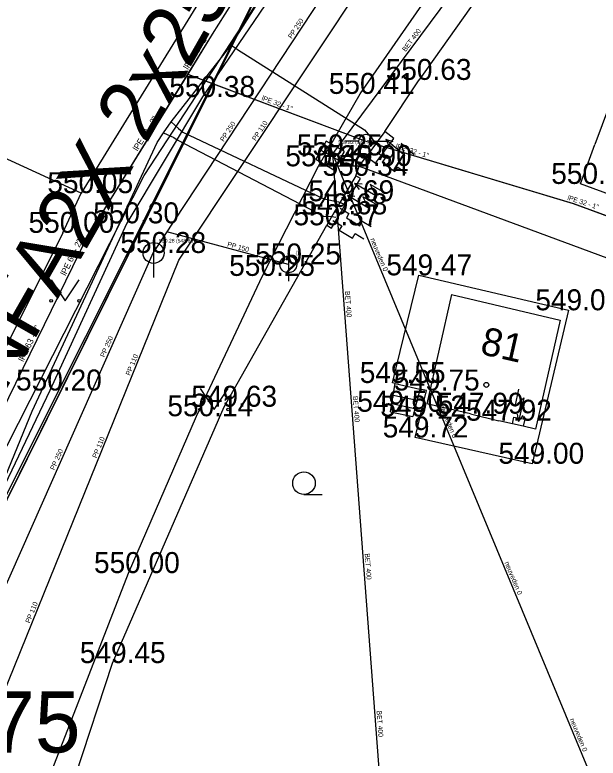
# Model space of a CAD drawing. Extents: x -669995 to -669686, y -1125551 to -1125263.
# Drawn here: x -669817.31 to -669796.45, y -1125325.67 to -1125299.08 of the extents above; entities that cross this region are included whole.
import ezdxf

# ---------------------------------------------------------------- set-up
doc = ezdxf.new("R2010")
doc.units = 0
for name, color, linetype in [('G_Bod_tecka', 7, 'Continuous'), ('G_Bod_vyska', 7, 'Continuous'), ('G_Budovy-znacky', 7, 'Continuous'), ('G_Budovy_Objekty', 7, 'Continuous'), ('G_Budovy_vstupy', 7, 'Continuous'), ('G_Cesty_Schody', 7, 'Continuous'), ('G_Cisla_jina', 7, 'Continuous'), ('G_Plochy_zpevnene', 7, 'Continuous'), ('G_Ploty', 7, 'Continuous'), ('G_Ploty_vstupy', 7, 'Continuous'), ('G_Site-kanalizace', 7, 'Continuous'), ('G_Site-Rozvadece', 7, 'Continuous'), ('G_Site-vodovod', 7, 'Continuous'), ('G_Z_ELsilove_nadz_kotovane', 7, 'Continuous'), ('G_Z_ELsilove_podz_kotovane', 7, 'Continuous'), ('G_Z_KANAL_podz_kotovane', 7, 'Continuous'), ('G_Z_KANAL_podz_priblizne', 7, 'Continuous'), ('G_Z_PLYNY_podz_geodeticky', 7, 'Continuous'), ('G_Z_SPOJE_podz_geodeticky', 7, 'Continuous'), ('G_Z_SPOJE_podz_kotovane', 7, 'Continuous'), ('G_Z_SPOJE_podz_priblizne', 7, 'Continuous'), ('G_Z_VODA_podz_kotovane', 7, 'Continuous'), ('G_Zelen-Znacky', 7, 'Continuous'), ('Vrstva 11', 7, 'Continuous'), ('Vrstva 17', 7, 'Continuous'), ('Vrstva 2', 7, 'Continuous'), ('Vrstva 21', 7, 'Continuous'), ('Vrstva 25', 7, 'Continuous'), ('Vrstva 26', 7, 'Continuous'), ('Vrstva 3', 7, 'Continuous'), ('Vrstva 4', 7, 'Continuous'), ('Vrstva 5', 7, 'Continuous'), ('Vrstva 6', 7, 'Continuous'), ('Vrstva 8', 7, 'Continuous')]:
    doc.layers.add(name, color=color, linetype=linetype)

msp = doc.modelspace()

# ---------------------------------------------------------------- linework, layer by layer
at = {"layer": 'G_Bod_tecka'}
for p, q in [((-669802.85, -1125301.41), (-669802.85, -1125301.41)), ((-669810.6, -1125302.02), (-669810.6, -1125302.02)), ((-669804.96, -1125301.91), (-669804.96, -1125301.91)), ((-669806.04, -1125304.11), (-669806.04, -1125304.11)), ((-669805, -1125304.49), (-669805, -1125304.49)), ((-669806.45, -1125304.5), (-669806.45, -1125304.5)), ((-669805.12, -1125304.84), (-669805.12, -1125304.84)), ((-669797.09, -1125305.13), (-669797.09, -1125305.13)), ((-669814.94, -1125305.46), (-669814.94, -1125305.46)), ((-669805.63, -1125305.75), (-669805.63, -1125305.75)), ((-669805.88, -1125306.22), (-669805.88, -1125306.22)), ((-669813.3, -1125306.54), (-669813.3, -1125306.54)), ((-669806.16, -1125306.61), (-669806.16, -1125306.61)), ((-669815.59, -1125306.88), (-669815.59, -1125306.88)), ((-669812.35, -1125307.6), (-669812.35, -1125307.6)), ((-669807.53, -1125308.01), (-669807.53, -1125308.01)), ((-669808.46, -1125308.42), (-669808.46, -1125308.42)), ((-669802.86, -1125308.4), (-669802.86, -1125308.4)), ((-669797.51, -1125309.65), (-669797.51, -1125309.65)), ((-669803.81, -1125312.25), (-669803.81, -1125312.25)), ((-669816.06, -1125312.52), (-669816.06, -1125312.52)), ((-669802.59, -1125312.52), (-669802.59, -1125312.52)), ((-669809.82, -1125313.1), (-669809.82, -1125313.1)), ((-669810.81, -1125313.44), (-669810.81, -1125313.44)), ((-669803.88, -1125313.28), (-669803.88, -1125313.28)), ((-669803.08, -1125313.45), (-669803.08, -1125313.45)), ((-669801.02, -1125313.35), (-669801.02, -1125313.35)), ((-669800.01, -1125313.6), (-669800.01, -1125313.6)), ((-669802.99, -1125314.2), (-669802.99, -1125314.2)), ((-669798.81, -1125315.14), (-669798.81, -1125315.14)), ((-669813.25, -1125319.05), (-669813.25, -1125319.05)), ((-669813.82, -1125322.27), (-669813.82, -1125322.27))]:
    msp.add_line(p, q, dxfattribs=at)
at = {"layer": 'G_Budovy-znacky'}
msp.add_circle((-669800.45, -1125312.32), 0.0875, dxfattribs=at)
at = {"layer": 'G_Budovy_Objekty'}
for p, q in [((-669797.09, -1125305.13), (-669796.57, -1125303.72)), ((-669782.72, -1125310.4), (-669797.09, -1125305.13)), ((-669803.81, -1125312.25), (-669802.86, -1125308.4)), ((-669802.86, -1125308.4), (-669797.51, -1125309.65)), ((-669801.7, -1125309.09), (-669802.58, -1125313)), ((-669801.7, -1125309.09), (-669797.81, -1125310)), ((-669797.51, -1125309.65), (-669798.81, -1125315.14)), ((-669797.81, -1125310), (-669798.69, -1125313.9)), ((-669803.71, -1125312.27), (-669803.81, -1125312.25)), ((-669802.99, -1125314.2), (-669802.59, -1125312.52)), ((-669802.59, -1125312.52), (-669802.83, -1125312.47)), ((-669801.02, -1125313.35), (-669802.58, -1125313)), ((-669799.52, -1125313.71), (-669800.01, -1125313.6)), ((-669799.13, -1125313.8), (-669799.52, -1125313.71)), ((-669798.69, -1125313.9), (-669799.13, -1125313.8)), ((-669798.81, -1125315.14), (-669802.99, -1125314.2))]:
    msp.add_line(p, q, dxfattribs=at)
at = {"layer": 'G_Budovy_vstupy'}
for p, q in [((-669794.77, -1125298.84), (-669796.57, -1125303.72)), ((-669803.71, -1125312.27), (-669802.83, -1125312.47)), ((-669801.02, -1125313.35), (-669800.01, -1125313.6))]:
    msp.add_line(p, q, dxfattribs=at)
at = {"layer": 'G_Cesty_Schody'}
for p, q in [((-669803.78, -1125312.69), (-669803.71, -1125312.27)), ((-669803.83, -1125312.98), (-669803.78, -1125312.69)), ((-669803.78, -1125312.69), (-669802.93, -1125312.87)), ((-669802.83, -1125312.47), (-669802.93, -1125312.87)), ((-669803.88, -1125313.28), (-669803.83, -1125312.98)), ((-669803.83, -1125312.98), (-669803.01, -1125313.16)), ((-669802.93, -1125312.87), (-669803.01, -1125313.16)), ((-669803.01, -1125313.16), (-669803.08, -1125313.45)), ((-669803.88, -1125313.28), (-669803.08, -1125313.45))]:
    msp.add_line(p, q, dxfattribs=at)
at = {"layer": 'G_Plochy_zpevnene'}
for p, q in [((-669804.96, -1125301.91), (-669801.82, -1125297.37)), ((-669806.45, -1125304.5), (-669804.96, -1125301.91)), ((-669808.46, -1125308.42), (-669806.45, -1125304.5)), ((-669810.81, -1125313.44), (-669808.46, -1125308.42)), ((-669813.25, -1125319.05), (-669810.81, -1125313.44)), ((-669818.19, -1125331.78), (-669813.25, -1125319.05))]:
    msp.add_line(p, q, dxfattribs=at)
for points in [[(-669805.79, -1125294.93), (-669810.6, -1125302.02), (-669813.3, -1125306.54), (-669816.06, -1125312.52), (-669819.42, -1125319.54), (-669819.78, -1125320.24), (-669820.3, -1125320.5), (-669820.46, -1125320.59)], [(-669805, -1125304.49), (-669806.45, -1125304.5)]]:
    msp.add_lwpolyline(points, dxfattribs=at)
at = {"layer": 'G_Ploty'}
for p, q in [((-669805, -1125304.49), (-669804.73, -1125304.15)), ((-669805, -1125304.49), (-669788.56, -1125310.6)), ((-669809.82, -1125313.1), (-669806.16, -1125306.61)), ((-669815.59, -1125306.88), (-669822.31, -1125320.3)), ((-669813.82, -1125322.27), (-669809.82, -1125313.1)), ((-669817.15, -1125332.43), (-669813.82, -1125322.27))]:
    msp.add_line(p, q, dxfattribs=at)
for points in [[(-669809.61, -1125296.8), (-669814.94, -1125305.46)], [(-669804.08, -1125303.26), (-669802.85, -1125301.41)], [(-669814.94, -1125305.46), (-669819.49, -1125303.38)], [(-669805.12, -1125304.84), (-669805, -1125304.49)]]:
    msp.add_lwpolyline(points, dxfattribs=at)
at = {"layer": 'G_Ploty_vstupy'}
msp.add_line((-669815.59, -1125306.88), (-669814.94, -1125305.46), dxfattribs=at)
msp.add_lwpolyline([(-669796.56, -1125292.52), (-669802.85, -1125301.41)], dxfattribs=at)
at = {"layer": 'G_Site-kanalizace'}
for p, q in [((-669806.366, -1125303.924), (-669805.714, -1125304.296)), ((-669812.35, -1125307.225), (-669812.35, -1125308.475)), ((-669807.53, -1125307.71), (-669807.53, -1125308.61))]:
    msp.add_line(p, q, dxfattribs=at)
msp.add_lwpolyline([(-669806.551, -1125304.249), (-669805.899, -1125304.621), (-669805.528, -1125303.969), (-669806.18, -1125303.598)], close=True, dxfattribs=at)
for centre, radius in [((-669812.35, -1125307.6), 0.375), ((-669807.53, -1125308.01), 0.3)]:
    msp.add_circle(centre, radius, dxfattribs=at)
at = {"layer": 'G_Site-Rozvadece'}
for p, q in [((-669803.382, -1125304.117), (-669804.04, -1125303.539)), ((-669803.783, -1125303.619), (-669804.04, -1125303.539)), ((-669804.04, -1125303.539), (-669803.928, -1125303.783)), ((-669803.029, -1125304.095), (-669803.499, -1125303.681)), ((-669803.499, -1125303.681), (-669803.382, -1125304.117)), ((-669804.405, -1125305.553), (-669805.16, -1125305.11)), ((-669804.893, -1125305.139), (-669805.16, -1125305.11)), ((-669805.16, -1125305.11), (-669805.004, -1125305.329)), ((-669804.062, -1125305.465), (-669804.602, -1125305.148)), ((-669804.602, -1125305.148), (-669804.405, -1125305.553)), ((-669804.665, -1125305.994), (-669805.42, -1125305.55)), ((-669805.153, -1125305.58), (-669805.42, -1125305.55)), ((-669805.42, -1125305.55), (-669805.264, -1125305.769)), ((-669804.322, -1125305.905), (-669804.862, -1125305.588)), ((-669804.862, -1125305.588), (-669804.665, -1125305.994)), ((-669799.296, -1125312.477), (-669799.434, -1125313.088)), ((-669799.434, -1125313.088), (-669799.107, -1125312.777)), ((-669799.107, -1125312.777), (-669799.3, -1125313.63)), ((-669799.52, -1125313.71), (-669799.47, -1125313.47)), ((-669799.47, -1125313.47), (-669799.08, -1125313.55)), ((-669799.353, -1125313.367), (-669799.3, -1125313.63)), ((-669799.3, -1125313.63), (-669799.139, -1125313.416)), ((-669799.08, -1125313.55), (-669799.13, -1125313.8))]:
    msp.add_line(p, q, dxfattribs=at)
for points in [[(-669803.76, -1125303.5), (-669804.08, -1125303.26), (-669804.32, -1125303.58), (-669804.73, -1125304.15), (-669804.41, -1125304.39), (-669803.99, -1125303.82)], [(-669805.12, -1125304.84), (-669805.38, -1125305.28), (-669805.64, -1125305.72), (-669805.9, -1125306.17), (-669806.16, -1125306.61), (-669805.99, -1125306.71), (-669805.73, -1125306.27), (-669805.47, -1125305.83), (-669805.21, -1125305.38), (-669804.95, -1125304.94)]]:
    msp.add_lwpolyline(points, close=True, dxfattribs=at)
for points in [[(-669804.36, -1125303.989), (-669804.063, -1125304.207), (-669804.171, -1125304.355), (-669803.725, -1125304.681), (-669803.617, -1125304.533), (-669803.319, -1125304.751)], [(-669805.68, -1125306), (-669805.363, -1125306.187), (-669805.456, -1125306.345), (-669804.98, -1125306.625), (-669804.886, -1125306.467), (-669804.568, -1125306.653)], [(-669805.94, -1125306.44), (-669805.623, -1125306.628), (-669805.716, -1125306.785), (-669805.24, -1125307.065), (-669805.146, -1125306.908), (-669804.828, -1125307.093)]]:
    msp.add_lwpolyline(points, dxfattribs=at)
at = {"layer": 'G_Site-vodovod'}
for p, q in [((-669805.01, -1125303.6), (-669805.51, -1125303.6)), ((-669804.51, -1125303.6), (-669804.01, -1125303.6))]:
    msp.add_line(p, q, dxfattribs=at)
msp.add_circle((-669804.76, -1125303.6), 0.25, dxfattribs=at)
at = {"layer": 'G_Z_ELsilove_nadz_kotovane'}
msp.add_lwpolyline([(-669822.83, -1125326.67), (-669806.73, -1125294.49), (-669793.764, -1125277.296)], dxfattribs=at)
at = {"layer": 'G_Z_ELsilove_podz_kotovane'}
msp.add_lwpolyline([(-669793.678, -1125277.309), (-669806.73, -1125294.49), (-669822.69, -1125326.67), (-669837.43, -1125364.93), (-669849.93, -1125407.07), (-669860.28, -1125448.68)], dxfattribs=at)
at = {"layer": 'G_Z_KANAL_podz_kotovane'}
for points in [[(-669837.47, -1125406.42), (-669844.1, -1125405.26), (-669833.36, -1125371.21), (-669821.31, -1125332.23), (-669811.44, -1125307.86), (-669795.39, -1125283.71), (-669791, -1125278.72), (-669790.199, -1125277.833)], [(-669796.02, -1125282.8), (-669812.36, -1125307.58), (-669819.67, -1125324.06)], [(-669807.53, -1125308.01), (-669811.87, -1125306.84), (-669811.87, -1125306.84)]]:
    msp.add_lwpolyline(points, dxfattribs=at)
at = {"layer": 'G_Z_KANAL_podz_priblizne'}
msp.add_line((-669805.95, -1125304.06), (-669791.39, -1125339.12), dxfattribs=at)
for points in [[(-669785.926, -1125278.477), (-669789.18, -1125282.01), (-669797.9, -1125293.2), (-669805.95, -1125304.06)], [(-669805.95, -1125304.06), (-669803.92, -1125330.96), (-669807.79, -1125366.49)]]:
    msp.add_lwpolyline(points, dxfattribs=at)
at = {"layer": 'G_Z_PLYNY_podz_geodeticky'}
for points in [[(-669837.38, -1125359.92), (-669836.39, -1125358.74), (-669831.49, -1125357.25), (-669831.11, -1125356.92), (-669827.75, -1125345.68), (-669825.44, -1125337.89), (-669825.15, -1125336.78), (-669824.89, -1125336.1), (-669824.26, -1125333.86), (-669824.2, -1125333.72), (-669824.11, -1125333.34), (-669824.01, -1125332.89), (-669822.73, -1125329.33), (-669822.53, -1125328.7), (-669820.54, -1125322.64), (-669816.69, -1125313.26), (-669812.22, -1125303.65), (-669812, -1125303.3), (-669811.72, -1125302.91), (-669809.57, -1125300.17), (-669804.79, -1125292.58), (-669800.14, -1125285.7), (-669795.88, -1125280.51), (-669793.302, -1125277.366)], [(-669809.57, -1125300.17), (-669809.41, -1125300.28), (-669809.35, -1125300.32), (-669804.81, -1125303.2), (-669804.49, -1125303.58), (-669804.31, -1125303.79)], [(-669811.72, -1125302.91), (-669811.46, -1125303.15), (-669811.3, -1125303.28), (-669806.26, -1125305.66), (-669805.74, -1125305.77), (-669805.58, -1125305.83)], [(-669812, -1125303.3), (-669811.63, -1125303.47), (-669811.5, -1125303.55), (-669806.27, -1125306.28), (-669805.98, -1125306.3), (-669805.83, -1125306.32)]]:
    msp.add_lwpolyline(points, dxfattribs=at)
at = {"layer": 'G_Z_SPOJE_podz_geodeticky'}
msp.add_lwpolyline([(-669821.65, -1125324.81), (-669819.63, -1125318.51), (-669812.69, -1125304.83), (-669803.17, -1125290.27), (-669793.576, -1125277.325)], dxfattribs=at)
at = {"layer": 'G_Z_SPOJE_podz_kotovane'}
msp.add_lwpolyline([(-669821.65, -1125324.81), (-669819.63, -1125318.51), (-669812.69, -1125304.83), (-669803.17, -1125290.27), (-669793.576, -1125277.325)], dxfattribs=at)
at = {"layer": 'G_Z_SPOJE_podz_priblizne'}
msp.add_lwpolyline([(-669821.65, -1125324.81), (-669819.63, -1125318.51), (-669812.69, -1125304.83), (-669803.17, -1125290.27), (-669793.576, -1125277.325)], dxfattribs=at)
at = {"layer": 'G_Z_VODA_podz_kotovane'}
msp.add_line((-669811.13, -1125301.2), (-669804.76, -1125303.6), dxfattribs=at)
for points in [[(-669793.904, -1125277.275), (-669806.05, -1125295.04), (-669809.12, -1125297.97), (-669810.25, -1125299.77), (-669811.13, -1125301.2), (-669814.74, -1125307.05), (-669820.1, -1125318), (-669821.98, -1125322.82), (-669822.36, -1125327.56), (-669822.7, -1125328.38), (-669827.24, -1125342.56), (-669833.54, -1125362.52), (-669834.09, -1125363.24)], [(-669804.76, -1125303.6), (-669797.34, -1125305.83), (-669784.7, -1125310.47), (-669784.44, -1125309.77)]]:
    msp.add_lwpolyline(points, dxfattribs=at)
at = {"layer": 'G_Zelen-Znacky'}
for p, q in [((-669816.01, -1125308.56), (-669815.51, -1125309.31)), ((-669815.51, -1125309.31), (-669815.01, -1125308.56)), ((-669810.68, -1125312.45), (-669810.18, -1125313.2)), ((-669810.18, -1125313.2), (-669809.68, -1125312.45)), ((-669806.972, -1125316.24), (-669806.322, -1125316.237))]:
    msp.add_line(p, q, dxfattribs=at)
for centre, radius in [((-669816.01, -1125309.31), 0.05), ((-669815.01, -1125309.31), 0.05), ((-669810.68, -1125313.2), 0.05), ((-669809.68, -1125313.2), 0.05), ((-669806.972, -1125315.837), 0.403)]:
    msp.add_circle(centre, radius, dxfattribs=at)
at = {"layer": 'Vrstva 11'}
for points in [[(-669796.02, -1125282.8), (-669812.36, -1125307.58), (-669819.67, -1125324.06)], [(-669807.53, -1125308.01), (-669811.87, -1125306.84), (-669811.872, -1125306.839)]]:
    msp.add_lwpolyline(points, dxfattribs=at)
at = {"layer": 'Vrstva 17'}
msp.add_line((-669805.95, -1125304.06), (-669791.39, -1125339.12), dxfattribs=at)
for points in [[(-669785.926, -1125278.477), (-669789.18, -1125282.01), (-669797.9, -1125293.2), (-669805.95, -1125304.06)], [(-669805.95, -1125304.06), (-669803.92, -1125330.96), (-669807.79, -1125366.49)]]:
    msp.add_lwpolyline(points, dxfattribs=at)
at = {"layer": 'Vrstva 21'}
msp.add_lwpolyline([(-669837.47, -1125406.42), (-669844.1, -1125405.26), (-669833.36, -1125371.21), (-669821.31, -1125332.23), (-669811.44, -1125307.86), (-669795.39, -1125283.71), (-669791, -1125278.72), (-669790.199, -1125277.833)], dxfattribs=at)
at = {"layer": 'Vrstva 25'}
msp.add_lwpolyline([(-669804.757, -1125303.601), (-669797.345, -1125305.832), (-669784.7, -1125310.475), (-669784.441, -1125309.771)], dxfattribs=at)
at = {"layer": 'Vrstva 26'}
msp.add_line((-669811.134, -1125301.203), (-669804.757, -1125303.601), dxfattribs=at)
msp.add_lwpolyline([(-669793.906, -1125277.275), (-669806.05, -1125295.04), (-669809.12, -1125297.97), (-669810.25, -1125299.77), (-669811.134, -1125301.203), (-669814.74, -1125307.05), (-669820.1, -1125318), (-669821.98, -1125322.82), (-669822.36, -1125327.56), (-669822.7, -1125328.38), (-669827.24, -1125342.56), (-669833.535, -1125362.519), (-669834.09, -1125363.24)], dxfattribs=at)
at = {"layer": 'Vrstva 5'}
msp.add_line((-669806.73, -1125294.49), (-669822.69, -1125326.67), dxfattribs=at)
at = {"layer": 'Vrstva 6'}
msp.add_line((-669804.757, -1125303.601), (-669804.757, -1125303.601), dxfattribs=at)
at = {"layer": 'Vrstva 8'}
for p, q in [((-669805.95, -1125304.06), (-669805.95, -1125304.06)), ((-669812.36, -1125307.58), (-669812.36, -1125307.58)), ((-669807.53, -1125308.01), (-669807.53, -1125308.01))]:
    msp.add_line(p, q, dxfattribs=at)

# ---------------------------------------------------------------- texts
at = {"layer": 'G_Bod_vyska'}
for s, p in [('550.63', (-669804.049, -1125301.41)), ('550.38', (-669811.786, -1125302.02)), ('550.41', (-669806.084, -1125301.91)), ('550.25', (-669807.226, -1125304.11)), ('550.35', (-669807.636, -1125304.5)), ('549.90', (-669806.187, -1125304.49)), ('550.34', (-669806.306, -1125304.84)), ('550.13', (-669798.131, -1125305.13)), ('550.05', (-669816.147, -1125305.46)), ('549.69', (-669806.812, -1125305.75)), ('549.68', (-669807.06, -1125306.22)), ('550.30', (-669814.507, -1125306.54)), ('550.37', (-669807.346, -1125306.61)), ('550.00', (-669816.819, -1125306.88)), ('550.28', (-669813.536, -1125307.6)), ('550.25', (-669808.716, -1125308.01)), ('550.25', (-669809.646, -1125308.42)), ('549.47', (-669804.026, -1125308.4)), ('549.02', (-669798.698, -1125309.65)), ('549.55', (-669804.976, -1125312.25)), ('550.20', (-669817.267, -1125312.52)), ('549.75', (-669803.756, -1125312.52)), ('549.63', (-669811, -1125313.1)), ('550.14', (-669811.854, -1125313.44)), ('549.50', (-669805.068, -1125313.28)), ('549.52', (-669804.246, -1125313.45)), ('547.99', (-669802.188, -1125313.35)), ('547.92', (-669801.176, -1125313.6)), ('549.72', (-669804.156, -1125314.2)), ('549.00', (-669800.019, -1125315.14)), ('550.00', (-669814.479, -1125319.05)), ('549.45', (-669814.986, -1125322.27))]:
    msp.add_text(s, height=0.75, dxfattribs=at).set_placement(p)
at = {"layer": 'G_Cisla_jina'}
msp.add_text('81', height=1, rotation=347.3275, dxfattribs=at).set_placement((-669800.709, -1125311.205))
at = {"layer": 'Vrstva 2'}
for s, height, p in [('549.82 (548.74)', 0.13163, (-669805.744, -1125303.707)), ('550.28 (548.66)', 0.13163, (-669812.154, -1125307.227)), ('\xa0()', 0.1316, (-669807.325, -1125307.657))]:
    msp.add_text(s, height=height, dxfattribs=at).set_placement(p)
at = {"layer": 'Vrstva 3'}
for s, height, rotation, p in [('NFA2X 2x25 2x25', 2.19389, 60.2692, (-669817.715, -1125312.66)), ('PP 250', 0.1755, 56.5958, (-669807.412, -1125299.949)), ('BET 400', 0.1755, 53.526, (-669803.336, -1125300.416)), ('PP 250', 0.1755, 56.6185, (-669809.843, -1125303.635)), ('PP 110', 0.1755, 56.4013, (-669808.699, -1125303.607)), ('neuveden 0', 0.1755, 292.5992, (-669804.607, -1125307.108)), ('PP 150', 0.1755, 344.8749, (-669809.728, -1125307.363)), ('BET 400', 0.1755, 274.3096, (-669805.509, -1125308.97)), ('PP 250', 0.1755, 66.1087, (-669814.108, -1125311.347)), ('PP 110', 0.1755, 67.8619, (-669813.193, -1125312.001)), ('BET 400', 0.1755, 274.3751, (-669805.226, -1125312.723)), ('neuveden 0', 0.1755, 292.5541, (-669802.133, -1125313.067)), ('PP 110', 0.1755, 67.8929, (-669814.388, -1125314.954)), ('PP 250', 0.1755, 66.0124, (-669815.898, -1125315.384)), ('BET 400', 0.1755, 274.3096, (-669804.8, -1125318.352)), ('neuveden 0', 0.1755, 292.5129, (-669799.804, -1125318.678)), ('PP 110', 0.1755, 67.9311, (-669816.78, -1125320.859)), ('BET 400', 0.1755, 274.307, (-669804.376, -1125323.979)), ('neuveden 0', 0.1755, 292.5222, (-669797.473, -1125324.287))]:
    msp.add_text(s, height=height, rotation=rotation, dxfattribs=at).set_placement(p)
at = {"layer": 'Vrstva 4'}
for s, height, rotation, p in [('lPE 63 - 2"', 0.21938, 58.2545, (-669811.116, -1125301.062)), ('lPE 32 - 1"', 0.17551, 339.5069, (-669808.501, -1125302.127)), ('lPE 63 - 2"', 0.21938, 58.2545, (-669812.92, -1125303.976)), ('lPE  32 - 1"', 0.17551, 343.3127, (-669803.709, -1125303.854)), ('lPE 32 - 1"', 0.17551, 342.0495, (-669797.567, -1125305.694)), ('lPE 63 - 2"', 0.21938, 63.9353, (-669815.494, -1125308.431)), ('lPE 63 - 2"', 0.21938, 63.916, (-669817.002, -1125311.509))]:
    msp.add_text(s, height=height, rotation=rotation, dxfattribs=at).set_placement(p)
msp.add_text('2275', height=2.1939, dxfattribs=at).set_placement((-669821.487, -1125325.469))

doc.saveas('drawing.dxf')
